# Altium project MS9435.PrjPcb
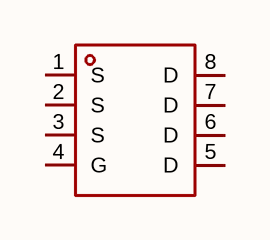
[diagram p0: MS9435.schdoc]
1 sheet, 1 parts. Net scope: global (net labels, ports and power ports of the same name join across sheets).

## Sheet MS9435.schdoc
size 127 x 101 mm

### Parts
Q?  ms9435  [SOP-8_L4.9-W3.9-P1.27-LS6.0-TL]  (value not drawn)

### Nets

Not connected (* = marked no-connect by the designer): Q? 1(S) 2(S) 3(S) 4(G) 5(D) 6(D) 7(D) 8(D)

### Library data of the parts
Q? = ms9435: 数量:1个P沟道;漏源电压(Vdss):30V;连续漏极电流(Id):5.3A;导通电阻(RDS(on)):50mΩ@10V;耗散功率(Pd):2.5W;阈值电压(Vgs(th)):3V;; Manufacturer: MSKSEMI(美森科); AddInBom: yes; ModelId: 4f1f5228684a45afaa7af8cce46001de; ModelName: SOP-8_L4.9-W3.9-H1.45-LS6.0-P1.27; ModelTransform: 236.22,189.751,0,0,0,0,-0.005,0.003,0; Number: 1个P沟道; Drain to Source Voltage: 30V; Current - Continuous Drain(Id): 5.3A; Pd - Power Dissipation: 2.5W; Gate Threshold Voltage (Vgs(th)): 3V; Gate Charge(Qg): 14nC@15V; Input Capacitance(Ciss): 690pF; Reverse Transfer Capacitance (Crss@Vds): 77pF; Type: P沟道; Output Capacitance(Coss): 306pF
